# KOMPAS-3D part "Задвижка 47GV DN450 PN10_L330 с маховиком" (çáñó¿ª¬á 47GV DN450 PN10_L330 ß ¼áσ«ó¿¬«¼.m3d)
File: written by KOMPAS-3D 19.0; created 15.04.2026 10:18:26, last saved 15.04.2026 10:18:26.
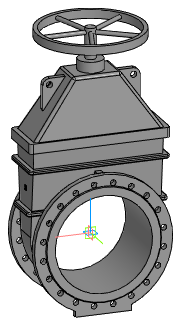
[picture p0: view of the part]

Document properties: Автор: Евгений; Полное имя файла: Z:\3.Личные\kachalov\3d для проектировщиков\2.1 Тип 47GV, 47GV.Z\Задвижка 47GV_DN40-DN600\stp_Задвижка 47GV\Задвижка 47GV DN450 PN10_L330 с маховиком.m3d

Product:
- Part/product: Задвижка 47GV DN450 PN10_L330 с маховиком

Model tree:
1. Операция без истории:1  (labels: Задвижка 47GV DN450 PN10_L330 с маховиком)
